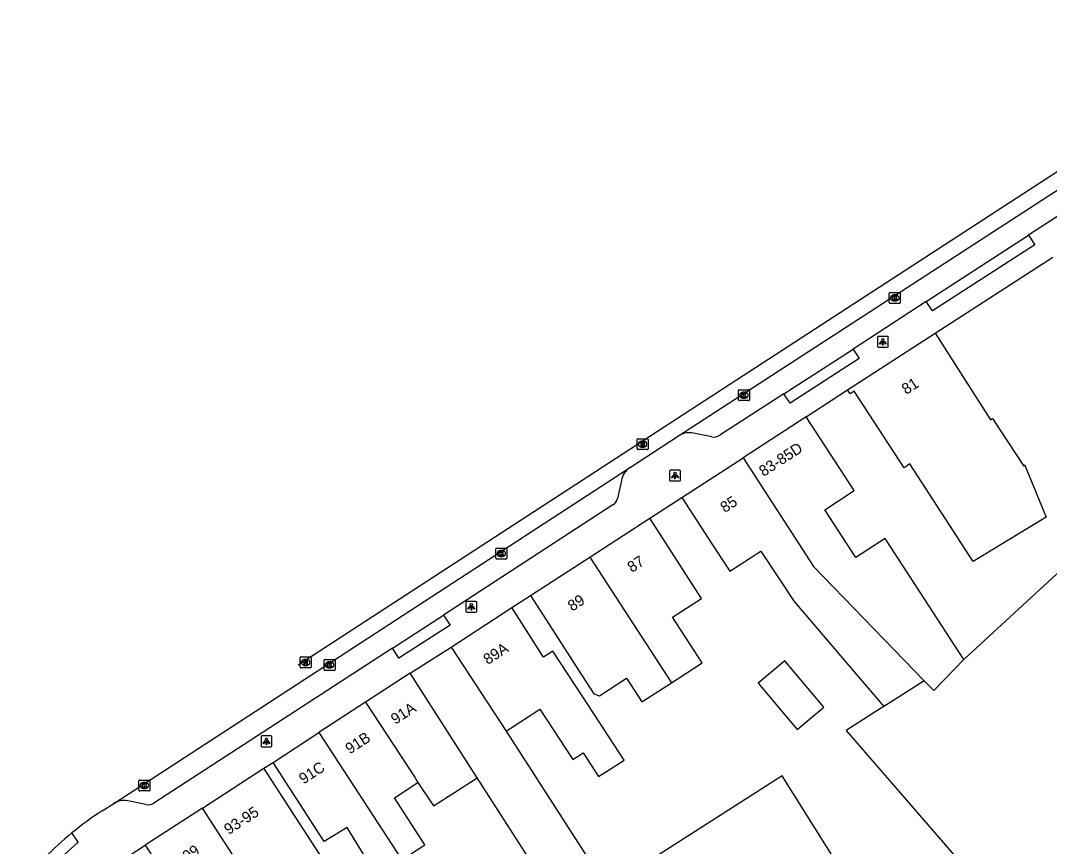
# Model space of a CAD drawing. Extents: x 159503 to 160347, y 382525 to 383272.
# Drawn here: x 159551.8 to 159645.8, y 383023.8 to 383099.4 of the extents above; entities that cross this region are included whole.
import ezdxf

# ---------------------------------------------------------------- set-up
doc = ezdxf.new("R2010")
doc.units = 0
for name, color, linetype in [('IMGEO_Fietspad_gesloten', 7, 'Continuous'), ('IMGEO_Kolk', 7, 'Continuous'), ('IMGEO_Lichtpunt', 7, 'Continuous'), ('IMGEO_Pand', 7, 'Continuous'), ('IMGEO_Pand_nummerreeks', 7, 'Continuous'), ('IMGEO_Rijbaan_lokaal_gesloten', 7, 'Continuous'), ('IMGEO_Rijbaan_lokaal_open', 7, 'Continuous'), ('IMGEO_Rioolput', 7, 'Continuous'), ('IMGEO_Voetpad_open', 7, 'Continuous')]:
    doc.layers.add(name, color=color, linetype=linetype)

msp = doc.modelspace()

# ---------------------------------------------------------------- linework, layer by layer
at = {"layer": 'IMGEO_Fietspad_gesloten'}
for points in [[(159612.015, 383061.42), (159670.445, 383099.353)], [(159607.448, 383058.44), (159612.015, 383061.42)], [(159560.278, 383027.743), (159607.448, 383058.44)], [(159559.232, 383027.069), (159560.278, 383027.743)]]:
    msp.add_lwpolyline(points, dxfattribs=at)
for centre, radius, start, end in [((159573.579, 383004.531), 26.717, 122.48022, 129.86819), ((159577.671, 382999.148), 33.473, 129.33739, 140.71147)]:
    msp.add_arc(centre, radius, start, end, dxfattribs=at)
at = {"layer": 'IMGEO_Kolk'}
for p, q in [((159631.19, 383073.557), (159631.19, 383074.409)), ((159631.265, 383074.483), (159632.117, 383074.483)), ((159632.191, 383074.409), (159632.191, 383073.557)), ((159632.117, 383073.483), (159631.265, 383073.483)), ((159631.701, 383073.703), (159631.676, 383073.703)), ((159631.678, 383074.263), (159631.703, 383074.263)), ((159617.395, 383064.658), (159617.395, 383065.51)), ((159617.47, 383065.584), (159618.322, 383065.584)), ((159617.883, 383065.364), (159617.908, 383065.364)), ((159618.396, 383065.51), (159618.396, 383064.658)), ((159618.322, 383064.584), (159617.47, 383064.584)), ((159617.906, 383064.804), (159617.881, 383064.804)), ((159595.211, 383050.172), (159595.211, 383051.024)), ((159595.286, 383051.098), (159596.138, 383051.098)), ((159595.699, 383050.878), (159595.724, 383050.878)), ((159596.212, 383051.024), (159596.212, 383050.172)), ((159596.138, 383050.098), (159595.286, 383050.098)), ((159595.722, 383050.318), (159595.697, 383050.318)), ((159579.51, 383039.985), (159579.51, 383040.837)), ((159579.585, 383040.911), (159580.437, 383040.911)), ((159579.998, 383040.691), (159580.023, 383040.691)), ((159580.511, 383040.837), (159580.511, 383039.985)), ((159580.437, 383039.911), (159579.585, 383039.911)), ((159580.021, 383040.131), (159579.996, 383040.131)), ((159562.58, 383028.957), (159562.58, 383029.809)), ((159562.655, 383029.883), (159563.507, 383029.883)), ((159563.068, 383029.663), (159563.093, 383029.663)), ((159563.581, 383029.809), (159563.581, 383028.957)), ((159563.507, 383028.883), (159562.655, 383028.883)), ((159563.091, 383029.103), (159563.066, 383029.103))]:
    msp.add_line(p, q, dxfattribs=at)
for points in [[(159631.19, 383073.557), (159631.19, 383074.409)], [(159631.265, 383074.483), (159632.117, 383074.483)], [(159632.191, 383074.409), (159632.191, 383073.557)], [(159632.117, 383073.483), (159631.265, 383073.483)], [(159631.511, 383074.183), (159631.634, 383074.183), (159631.634, 383074.032), (159631.764, 383074.183), (159631.928, 383074.183), (159631.782, 383074.032), (159631.935, 383073.783), (159631.783, 383073.783), (159631.698, 383073.947), (159631.634, 383073.88), (159631.634, 383073.783), (159631.511, 383073.783), (159631.511, 383074.183)], [(159617.395, 383064.658), (159617.395, 383065.51)], [(159617.47, 383065.584), (159618.322, 383065.584)], [(159617.716, 383065.284), (159617.839, 383065.284), (159617.839, 383065.133), (159617.969, 383065.284), (159618.133, 383065.284), (159617.987, 383065.133), (159618.14, 383064.884), (159617.988, 383064.884), (159617.903, 383065.048), (159617.839, 383064.981), (159617.839, 383064.884), (159617.716, 383064.884), (159617.716, 383065.284)], [(159618.396, 383065.51), (159618.396, 383064.658)], [(159618.322, 383064.584), (159617.47, 383064.584)], [(159595.211, 383050.172), (159595.211, 383051.024)], [(159595.286, 383051.098), (159596.138, 383051.098)], [(159596.212, 383051.024), (159596.212, 383050.172)], [(159596.138, 383050.098), (159595.286, 383050.098)], [(159595.532, 383050.798), (159595.655, 383050.798), (159595.655, 383050.647), (159595.785, 383050.798), (159595.949, 383050.798), (159595.803, 383050.647), (159595.956, 383050.398), (159595.804, 383050.398), (159595.719, 383050.562), (159595.655, 383050.495), (159595.655, 383050.398), (159595.532, 383050.398), (159595.532, 383050.798)], [(159579.51, 383039.985), (159579.51, 383040.837)], [(159579.585, 383040.911), (159580.437, 383040.911)], [(159579.831, 383040.611), (159579.954, 383040.611), (159579.954, 383040.46), (159580.084, 383040.611), (159580.248, 383040.611), (159580.102, 383040.46), (159580.255, 383040.211), (159580.103, 383040.211), (159580.018, 383040.375), (159579.954, 383040.308), (159579.954, 383040.211), (159579.831, 383040.211), (159579.831, 383040.611)], [(159580.511, 383040.837), (159580.511, 383039.985)], [(159580.437, 383039.911), (159579.585, 383039.911)], [(159562.58, 383028.957), (159562.58, 383029.809)], [(159562.655, 383029.883), (159563.507, 383029.883)], [(159562.901, 383029.583), (159563.024, 383029.583), (159563.024, 383029.432), (159563.154, 383029.583), (159563.318, 383029.583), (159563.172, 383029.432), (159563.325, 383029.183), (159563.173, 383029.183), (159563.088, 383029.347), (159563.024, 383029.28), (159563.024, 383029.183), (159562.901, 383029.183), (159562.901, 383029.583)], [(159563.581, 383029.809), (159563.581, 383028.957)], [(159563.507, 383028.883), (159562.655, 383028.883)]]:
    msp.add_lwpolyline(points, dxfattribs=at)
for centre, start, end in [((159631.267, 383074.407), 91.55205, 178.44795), ((159631.267, 383074.407), 91.55205, 178.44795), ((159632.115, 383074.407), 1.55205, 88.44795), ((159632.115, 383074.407), 1.55205, 88.44795), ((159631.267, 383073.559), 181.55205, 268.44795), ((159631.267, 383073.559), 181.55205, 268.44795), ((159632.115, 383073.559), 271.55205, 358.44795), ((159632.115, 383073.559), 271.55205, 358.44795), ((159617.472, 383065.508), 91.55205, 178.44795), ((159617.472, 383065.508), 91.55205, 178.44795), ((159618.32, 383065.508), 1.55205, 88.44795), ((159618.32, 383065.508), 1.55205, 88.44795), ((159617.472, 383064.66), 181.55205, 268.44795), ((159617.472, 383064.66), 181.55205, 268.44795), ((159618.32, 383064.66), 271.55205, 358.44795), ((159618.32, 383064.66), 271.55205, 358.44795), ((159595.288, 383051.022), 91.55205, 178.44795), ((159595.288, 383051.022), 91.55205, 178.44795), ((159596.136, 383051.022), 1.55205, 88.44795), ((159596.136, 383051.022), 1.55205, 88.44795), ((159595.288, 383050.174), 181.55205, 268.44795), ((159595.288, 383050.174), 181.55205, 268.44795), ((159596.136, 383050.174), 271.55205, 358.44795), ((159596.136, 383050.174), 271.55205, 358.44795), ((159579.587, 383040.835), 91.55205, 178.44795), ((159579.587, 383040.835), 91.55205, 178.44795), ((159580.435, 383040.835), 1.55205, 88.44795), ((159580.435, 383040.835), 1.55205, 88.44795), ((159579.587, 383039.987), 181.55205, 268.44795), ((159579.587, 383039.987), 181.55205, 268.44795), ((159580.435, 383039.987), 271.55205, 358.44795), ((159580.435, 383039.987), 271.55205, 358.44795), ((159562.657, 383029.807), 91.55205, 178.44795), ((159562.657, 383029.807), 91.55205, 178.44795), ((159563.505, 383029.807), 1.55205, 88.44795), ((159563.505, 383029.807), 1.55205, 88.44795), ((159562.657, 383028.959), 181.55205, 268.44795), ((159562.657, 383028.959), 181.55205, 268.44795), ((159563.505, 383028.959), 271.55205, 358.44795), ((159563.505, 383028.959), 271.55205, 358.44795)]:
    msp.add_arc(centre, 0.0765, start, end, dxfattribs=at)
for centre, major_axis, ratio, start_param, end_param in [((159631.677, 383073.983), (-0.387, 0.002), 0.722429, 4.712389, 7.853982), ((159631.702, 383073.983), (-0.39, 0.002), 0.717154, 1.570796, 4.712389), ((159617.882, 383065.084), (-0.387, 0.002), 0.722429, 4.712389, 7.853982), ((159617.907, 383065.084), (-0.39, 0.002), 0.717154, 1.570796, 4.712389), ((159595.698, 383050.598), (-0.387, 0.002), 0.722429, 4.712389, 7.853982), ((159595.723, 383050.598), (-0.39, 0.002), 0.717154, 1.570796, 4.712389), ((159579.997, 383040.411), (-0.387, 0.002), 0.722429, 4.712389, 7.853982), ((159580.022, 383040.411), (-0.39, 0.002), 0.717154, 1.570796, 4.712389), ((159563.067, 383029.383), (-0.387, 0.002), 0.722429, 4.712389, 7.853982), ((159563.092, 383029.383), (-0.39, 0.002), 0.717154, 1.570796, 4.712389)]:
    msp.add_ellipse(centre, major_axis=major_axis, ratio=ratio, start_param=start_param, end_param=end_param, dxfattribs=at)
at = {"layer": 'IMGEO_Lichtpunt'}
for p, q in [((159630.103, 383070.372), (159630.103, 383069.565)), ((159630.103, 383070.372), (159630.103, 383069.565)), ((159631.005, 383070.467), (159630.197, 383070.467)), ((159631.005, 383070.467), (159630.197, 383070.467)), ((159631.099, 383069.565), (159631.099, 383070.372)), ((159631.099, 383069.565), (159631.099, 383070.372)), ((159630.197, 383069.471), (159631.005, 383069.471)), ((159630.197, 383069.471), (159631.005, 383069.471)), ((159611.1, 383058.139), (159611.1, 383057.332)), ((159611.1, 383058.139), (159611.1, 383057.332)), ((159612.002, 383058.234), (159611.194, 383058.234)), ((159612.002, 383058.234), (159611.194, 383058.234)), ((159612.096, 383057.332), (159612.096, 383058.139)), ((159612.096, 383057.332), (159612.096, 383058.139)), ((159611.194, 383057.238), (159612.002, 383057.238)), ((159611.194, 383057.238), (159612.002, 383057.238)), ((159593.371, 383046.225), (159592.563, 383046.225)), ((159593.371, 383046.225), (159592.563, 383046.225)), ((159592.469, 383046.13), (159592.469, 383045.323)), ((159592.469, 383046.13), (159592.469, 383045.323)), ((159593.465, 383045.323), (159593.465, 383046.13)), ((159593.465, 383045.323), (159593.465, 383046.13)), ((159592.563, 383045.229), (159593.371, 383045.229)), ((159592.563, 383045.229), (159593.371, 383045.229)), ((159573.745, 383033.829), (159573.745, 383033.022)), ((159573.745, 383033.829), (159573.745, 383033.022)), ((159574.647, 383033.924), (159573.839, 383033.924)), ((159574.647, 383033.924), (159573.839, 383033.924)), ((159574.741, 383033.022), (159574.741, 383033.829)), ((159574.741, 383033.022), (159574.741, 383033.829)), ((159573.839, 383032.928), (159574.647, 383032.928)), ((159573.839, 383032.928), (159574.647, 383032.928))]:
    msp.add_line(p, q, dxfattribs=at)
for points in [[(159630.477, 383070.036), (159630.516, 383070.008), (159630.328, 383069.746), (159630.29, 383069.773), (159630.477, 383070.036)], [(159630.579, 383069.988), (159630.626, 383069.988), (159630.626, 383069.666), (159630.579, 383069.666), (159630.579, 383069.988)], [(159630.689, 383070.008), (159630.727, 383070.035), (159630.914, 383069.773), (159630.875, 383069.745), (159630.689, 383070.008)], [(159611.474, 383057.803), (159611.513, 383057.775), (159611.325, 383057.513), (159611.287, 383057.54), (159611.474, 383057.803)], [(159611.576, 383057.755), (159611.623, 383057.755), (159611.623, 383057.433), (159611.576, 383057.433), (159611.576, 383057.755)], [(159611.686, 383057.775), (159611.724, 383057.802), (159611.911, 383057.54), (159611.872, 383057.512), (159611.686, 383057.775)], [(159592.843, 383045.794), (159592.882, 383045.766), (159592.694, 383045.504), (159592.656, 383045.531), (159592.843, 383045.794)], [(159592.945, 383045.746), (159592.992, 383045.746), (159592.992, 383045.424), (159592.945, 383045.424), (159592.945, 383045.746)], [(159593.055, 383045.766), (159593.093, 383045.793), (159593.28, 383045.531), (159593.241, 383045.503), (159593.055, 383045.766)], [(159574.119, 383033.493), (159574.158, 383033.465), (159573.97, 383033.203), (159573.932, 383033.23), (159574.119, 383033.493)], [(159574.221, 383033.445), (159574.268, 383033.445), (159574.268, 383033.123), (159574.221, 383033.123), (159574.221, 383033.445)], [(159574.331, 383033.465), (159574.369, 383033.492), (159574.556, 383033.23), (159574.517, 383033.202), (159574.331, 383033.465)]]:
    msp.add_lwpolyline(points, dxfattribs=at)
for centre in [(159630.602, 383070.17), (159611.599, 383057.937), (159592.968, 383045.928), (159574.244, 383033.627)]:
    msp.add_circle(centre, 0.0994, dxfattribs=at)
for centre, start, end in [((159630.197, 383070.372), 90, 180), ((159630.197, 383070.372), 90, 180), ((159631.005, 383070.372), 0, 90), ((159631.005, 383070.372), 0, 90), ((159630.197, 383069.565), 180, 270), ((159630.197, 383069.565), 180, 270), ((159631.005, 383069.565), 270, 0), ((159631.005, 383069.565), 270, 360), ((159611.194, 383058.139), 90, 180), ((159611.194, 383058.139), 90, 180), ((159612.002, 383058.139), 0, 90), ((159612.002, 383058.139), 0, 90), ((159611.194, 383057.332), 180, 270), ((159611.194, 383057.332), 180, 270), ((159612.002, 383057.332), 270, 0), ((159612.002, 383057.332), 270, 360), ((159592.563, 383046.13), 90, 180), ((159592.563, 383046.13), 90, 180), ((159593.371, 383046.13), 0, 90), ((159593.371, 383046.13), 0, 90), ((159592.563, 383045.323), 180, 270), ((159592.563, 383045.323), 180, 270), ((159593.371, 383045.323), 270, 0), ((159593.371, 383045.323), 270, 360), ((159573.839, 383033.829), 90, 180), ((159573.839, 383033.829), 90, 180), ((159573.839, 383033.022), 180, 270), ((159573.839, 383033.022), 180, 270), ((159574.647, 383033.829), 0, 90), ((159574.647, 383033.829), 0, 90), ((159574.647, 383033.022), 270, 0), ((159574.647, 383033.022), 270, 360)]:
    msp.add_arc(centre, 0.0946, start, end, dxfattribs=at)
at = {"layer": 'IMGEO_Pand'}
for points in [[(159627.36, 383065.564), (159635.381, 383070.759)], [(159635.381, 383070.759), (159640.436, 383062.834), (159640.637, 383062.964), (159643.476, 383058.598), (159643.546, 383058.737), (159645.528, 383053.927), (159638.861, 383049.879), (159633.067, 383058.793), (159632.533, 383058.445), (159627.972, 383065.458), (159627.598, 383065.208), (159627.36, 383065.564)], [(159623.573, 383063.107), (159617.822, 383059.369)], [(159638.017, 383040.912), (159630.82, 383051.977), (159628.138, 383050.233), (159625.292, 383054.608), (159627.974, 383056.353), (159623.573, 383063.107)], [(159612.212, 383055.722), (159617.822, 383059.369)], [(159617.822, 383059.369), (159624.261, 383049.4), (159634.39, 383038.945)], [(159612.212, 383055.722), (159614.972, 383051.477), (159616.599, 383048.975), (159619.43, 383050.816), (159622.488, 383046.215), (159627.078, 383040.822), (159630.675, 383036.596)], [(159603.811, 383050.283), (159609.308, 383053.844)], [(159611.284, 383038.781), (159614.071, 383040.592), (159611.358, 383044.768), (159614.025, 383046.501), (159609.308, 383053.844)], [(159651.431, 383053.278), (159638.017, 383040.912)], [(159598.389, 383046.77), (159603.811, 383050.283)], [(159603.811, 383050.283), (159611.284, 383038.781)], [(159598.389, 383046.77), (159603.105, 383039.424), (159604.17, 383037.765), (159604.697, 383037.594), (159607.173, 383039.187), (159608.578, 383037.023), (159611.284, 383038.781)], [(159591.119, 383042.048), (159596.69, 383045.666)], [(159596.147, 383034.355), (159599.239, 383036.37), (159602.25, 383031.752), (159603.198, 383032.37), (159604.616, 383030.193), (159605.337, 383030.663), (159606.935, 383031.705), (159603.167, 383037.488), (159600.437, 383041.676), (159599.579, 383041.118), (159596.69, 383045.666)], [(159591.119, 383042.048), (159596.147, 383034.355)], [(159621.633, 383040.794), (159619.2, 383038.744), (159622.775, 383034.502), (159625.19, 383036.538), (159621.633, 383040.794)], [(159638.017, 383040.912), (159635.268, 383038.058), (159634.39, 383038.945)], [(159587.395, 383039.667), (159583.31, 383037.008)], [(159593.507, 383030.078), (159587.395, 383039.667)], [(159634.39, 383038.945), (159631.993, 383037.429), (159630.675, 383036.596)], [(159583.31, 383037.008), (159579.027, 383034.22)], [(159583.31, 383037.008), (159587.826, 383030.086), (159588.098, 383029.67)], [(159630.675, 383036.596), (159629.723, 383035.994), (159627.256, 383034.416), (159641.831, 383017.554), (159645.1, 383013.771)], [(159574.845, 383031.499), (159579.027, 383034.22)], [(159579.027, 383034.22), (159586.617, 383022.585)], [(159586.617, 383022.585), (159587.738, 383020.879), (159585.363, 383019.431), (159584.722, 383020.483), (159584.461, 383020.911), (159581.635, 383025.545), (159579.532, 383024.263), (159574.845, 383031.499)], [(159568.383, 383027.302), (159574.012, 383030.96)], [(159580.786, 383013.624), (159579.654, 383015.369), (159579.789, 383015.457), (159576.79, 383020.079), (159579.787, 383022.025), (159574.012, 383030.96)], [(159635.355, 383008.004), (159621.4, 383030.261), (159609.307, 383022.512)], [(159586.617, 383022.585), (159588.736, 383023.968), (159585.936, 383028.26), (159588.098, 383029.67)], [(159588.098, 383029.67), (159589.515, 383027.507), (159591.519, 383028.798), (159593.507, 383030.078)], [(159568.383, 383027.302), (159563.163, 383023.911)], [(159578.308, 383012.015), (159568.383, 383027.302)], [(159558.995, 383021.203), (159563.163, 383023.911)], [(159563.163, 383023.911), (159568.983, 383014.938)]]:
    msp.add_lwpolyline(points, dxfattribs=at)
at = {"layer": 'IMGEO_Rijbaan_lokaal_gesloten'}
msp.add_lwpolyline([(159577.133, 383040.415), (159579.577, 383042.002), (159613.053, 383063.788), (159650.536, 383088.143), (159655.033, 383090.963), (159657.783, 383092.738)], dxfattribs=at)
at = {"layer": 'IMGEO_Rijbaan_lokaal_open'}
for points in [[(159587.395, 383039.667), (159591.119, 383042.048)], [(159596.147, 383034.355), (159604.136, 383021.944)], [(159599.831, 383020.269), (159593.507, 383030.078)]]:
    msp.add_lwpolyline(points, dxfattribs=at)
at = {"layer": 'IMGEO_Rioolput'}
for p, q in [((159608.13, 383060.178), (159608.13, 383061.03)), ((159608.205, 383061.104), (159609.057, 383061.104)), ((159608.641, 383060.324), (159608.616, 383060.324)), ((159608.618, 383060.884), (159608.643, 383060.884)), ((159609.131, 383061.03), (159609.131, 383060.178)), ((159609.057, 383060.104), (159608.205, 383060.104)), ((159577.316, 383040.214), (159577.316, 383041.066)), ((159577.391, 383041.14), (159578.243, 383041.14)), ((159577.804, 383040.92), (159577.829, 383040.92)), ((159578.317, 383041.066), (159578.317, 383040.214)), ((159578.243, 383040.14), (159577.391, 383040.14)), ((159577.827, 383040.36), (159577.802, 383040.36))]:
    msp.add_line(p, q, dxfattribs=at)
for points in [[(159608.13, 383060.178), (159608.13, 383061.03)], [(159608.205, 383061.104), (159609.057, 383061.104)], [(159608.719, 383060.802), (159608.467, 383060.804), (159608.467, 383060.404)], [(159608.467, 383060.404), (159608.591, 383060.404), (159608.591, 383060.566), (159608.602, 383060.566)], [(159608.645, 383060.723), (159608.591, 383060.723), (159608.591, 383060.642)], [(159608.591, 383060.642), (159608.643, 383060.642)], [(159608.649, 383060.537), (159608.72, 383060.404), (159608.86, 383060.404), (159608.795, 383060.53)], [(159609.131, 383061.03), (159609.131, 383060.178)], [(159609.057, 383060.104), (159608.205, 383060.104)], [(159577.316, 383040.214), (159577.316, 383041.066)], [(159577.391, 383041.14), (159578.243, 383041.14)], [(159577.905, 383040.838), (159577.653, 383040.84), (159577.653, 383040.44)], [(159577.653, 383040.44), (159577.777, 383040.44), (159577.777, 383040.602), (159577.788, 383040.602)], [(159577.831, 383040.759), (159577.777, 383040.759), (159577.777, 383040.678)], [(159577.777, 383040.678), (159577.829, 383040.678)], [(159577.835, 383040.573), (159577.906, 383040.44), (159578.046, 383040.44), (159577.981, 383040.566)], [(159578.317, 383041.066), (159578.317, 383040.214)], [(159578.243, 383040.14), (159577.391, 383040.14)]]:
    msp.add_lwpolyline(points, dxfattribs=at)
for centre, radius, start, end in [((159608.207, 383061.028), 0.0765, 91.55205, 178.44795), ((159608.207, 383061.028), 0.0765, 91.55205, 178.44795), ((159608.601, 383060.513), 0.0533, 26.02933, 88.69889), ((159608.627, 383060.831), 0.19, 274.7715, 282.96867), ((159608.651, 383060.627), 0.0964, 77.00612, 93.18647), ((159608.665, 383060.684), 0.0378, 276.66336, 79.67722), ((159608.718, 383060.692), 0.109, 350.36119, 89.41601), ((159608.716, 383060.692), 0.112, 277.58423, 350.98172), ((159608.7, 383060.477), 0.108, 29.51342, 73.79051), ((159609.055, 383061.028), 0.0765, 1.55205, 88.44795), ((159609.055, 383061.028), 0.0765, 1.55205, 88.44795), ((159608.207, 383060.18), 0.0765, 181.55205, 268.44795), ((159608.207, 383060.18), 0.0765, 181.55205, 268.44795), ((159609.055, 383060.18), 0.0765, 271.55205, 358.44795), ((159609.055, 383060.18), 0.0765, 271.55205, 358.44795), ((159577.393, 383041.064), 0.0765, 91.55205, 178.44795), ((159577.393, 383041.064), 0.0765, 91.55205, 178.44795), ((159577.787, 383040.549), 0.0533, 26.02933, 88.69889), ((159577.813, 383040.867), 0.19, 274.7715, 282.96867), ((159577.837, 383040.663), 0.0964, 77.00612, 93.18647), ((159577.851, 383040.72), 0.0378, 276.66336, 79.67722), ((159577.904, 383040.728), 0.109, 350.36119, 89.41601), ((159577.902, 383040.728), 0.112, 277.58423, 350.98172), ((159577.886, 383040.513), 0.108, 29.51342, 73.79051), ((159578.241, 383041.064), 0.0765, 1.55205, 88.44795), ((159578.241, 383041.064), 0.0765, 1.55205, 88.44795), ((159577.393, 383040.216), 0.0765, 181.55205, 268.44795), ((159577.393, 383040.216), 0.0765, 181.55205, 268.44795), ((159578.241, 383040.216), 0.0765, 271.55205, 358.44795), ((159578.241, 383040.216), 0.0765, 271.55205, 358.44795)]:
    msp.add_arc(centre, radius, start, end, dxfattribs=at)
for centre, major_axis, ratio, start_param, end_param in [((159608.617, 383060.604), (-0.387, 0.002), 0.722429, 4.712389, 7.853982), ((159608.642, 383060.604), (-0.39, 0.002), 0.717154, 1.570796, 4.712389), ((159577.803, 383040.64), (-0.387, 0.002), 0.722429, 4.712389, 7.853982), ((159577.828, 383040.64), (-0.39, 0.002), 0.717154, 1.570796, 4.712389)]:
    msp.add_ellipse(centre, major_axis=major_axis, ratio=ratio, start_param=start_param, end_param=end_param, dxfattribs=at)
at = {"layer": 'IMGEO_Voetpad_open'}
for points in [[(159669.075, 383096.07), (159643.904, 383079.714)], [(159643.904, 383079.714), (159644.484, 383078.837), (159635.122, 383072.796), (159634.55, 383073.649)], [(159634.55, 383073.649), (159643.904, 383079.714)], [(159635.381, 383070.759), (159646.126, 383077.716)], [(159634.55, 383073.649), (159627.878, 383069.302)], [(159627.878, 383069.302), (159628.446, 383068.442), (159622.133, 383064.36), (159621.553, 383065.216)], [(159621.553, 383065.216), (159627.878, 383069.302)], [(159621.553, 383065.216), (159615.691, 383061.422)], [(159623.573, 383063.107), (159627.36, 383065.564)], [(159614.952, 383061.271), (159613.296, 383061.614)], [(159606.701, 383057.29), (159606.329, 383055.649)], [(159609.308, 383053.844), (159612.212, 383055.722)], [(159605.898, 383055.045), (159590.437, 383044.957)], [(159596.69, 383045.666), (159598.389, 383046.77)], [(159590.437, 383044.957), (159591.029, 383044.054), (159586.345, 383041.041), (159585.776, 383041.931)], [(159585.776, 383041.931), (159590.437, 383044.957)], [(159585.776, 383041.931), (159563.949, 383027.779)], [(159574.012, 383030.96), (159574.845, 383031.499)], [(159563.207, 383027.64), (159561.568, 383027.974)], [(159555.783, 383023.083), (159557.017, 383024.193), (159556.453, 383025.037)]]:
    msp.add_lwpolyline(points, dxfattribs=at)
for centre, radius, start, end in [((159612.905, 383059.868), 1.789, 77.3802, 119.84315), ((159615.154, 383062.165), 0.916, 257.24861, 305.84797), ((159608.41, 383056.997), 1.734, 123.70157, 170.28572), ((159605.431, 383055.834), 0.917, 300.6224, 348.3561), ((159561.232, 383026.132), 1.873, 79.67143, 120.63325), ((159563.419, 383028.558), 0.942, 256.98625, 304.23441)]:
    msp.add_arc(centre, radius, start, end, dxfattribs=at)

# ---------------------------------------------------------------- texts
at = {"layer": 'IMGEO_Pand_nummerreeks'}
for s, rotation, p in [('81', 33.02227, (159632.732, 383065.103)), ('83-85D', 33.02529, (159619.688, 383057.6)), ('85', 33.03675, (159616.147, 383054.292)), ('87', 33.01094, (159607.653, 383048.822)), ('89', 33.0081, (159602.2, 383045.279)), ('89A', 33.05966, (159594.48, 383040.386)), ('91A', 33.04081, (159586.029, 383034.926)), ('91B', 33.03703, (159581.866, 383032.22)), ('91C', 33.03675, (159577.633, 383029.466)), ('93-95', 32.97869, (159570.781, 383024.84)), ('97-99', 32.97945, (159565.362, 383021.324))]:
    msp.add_text(s, height=1, rotation=rotation, dxfattribs=at).set_placement(p)

doc.saveas('drawing.dxf')
